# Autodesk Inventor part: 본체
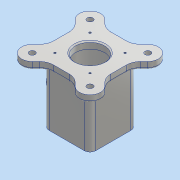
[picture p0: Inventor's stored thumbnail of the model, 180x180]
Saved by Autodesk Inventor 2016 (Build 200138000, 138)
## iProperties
Created: 2019-11
Part Number: 본체
Material: 알루미늄 6061
Document SubType Name: Modeling
Designer: user
Density: 2.7 g/cm^3
Appearance: 알루미늄 - 평지
Mass: 1074.3 g
Surface Area: 878.245 cm^2
Volume: 397.89 cm^3
Author: user
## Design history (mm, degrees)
sketch "스케치1"
  geometry: L1 (49, -49)-(-49, -49); L2 (-49, -49)-(-49, 49); L3 (-49, 49)-(49, 49); L4 (49, 49)-(49, -49); L5 (49, -49)-(-49, 49); L6 (-49, -49)-(49, 49); L7 (49.497, -49.497)-(-49.497, 49.497); L8 (62.225, -36.77)-(-36.77, 62.225); L9 (-62.225, 36.77)-(36.77, -62.225); L10 (-49.497, -49.497)-(49.497, 49.497); L11 (-36.77, -62.225)-(62.225, 36.77); L12 (36.77, 62.225)-(-62.225, -36.77); A1 r 18 centre (49.497, -49.497) between (36.77, -62.225) and (62.225, -36.77); A2 r 18 centre (-49.497, 49.497) between (-36.77, 62.225) and (-62.225, 36.77); A3 r 18 centre (-49.497, -49.497) between (-62.225, -36.77) and (-36.77, -62.225); A4 r 18 centre (49.497, 49.497) between (62.225, 36.77) and (36.77, 62.225); 1 further point
  constraints: 28 end point, 8 point on circle, 8 tangent, 4 centre point, 4 midpoint, 4 parallel, 2 point on line, 1 horizontal, 1 perpendicular
  dimensions: "d0" = 98 distance of L2.end L3.end; "d1" = 98 distance of L3.end L1.start; "d2" = 36 distance between parallel lines of L11 L12; "d3" = 36 distance between parallel lines of L9 L8; "d4" = 70 distance of L7.start point (0, 0); "d5" = 70 distance of L10.start point (0, 0)
extrude "돌출1" new body sketch "스케치1" distance "d6" = 12; taper "d7" = 0 deg
sketch "스케치2"
  geometry: L1 (30, -30)-(-30, -30); L2 (-30, -30)-(-30, 30); L3 (-30, 30)-(30, 30); L4 (30, 30)-(30, -30); L5 (30, -30)-(-30, 30); L6 (-30, -30)-(30, 30); L7 (23.544, 49)-(-23.544, 49) reference; L8 (-23.544, 49)-(-36.77, 62.225) reference; L9 (-62.225, 36.77)-(-49, 23.544) reference; L10 (-49, 23.544)-(-49, -23.544) reference; L11 (-49, -23.544)-(-62.225, -36.77) reference; L12 (-36.77, -62.225)-(-23.544, -49) reference; L13 (-23.544, -49)-(23.544, -49) reference; L14 (23.544, -49)-(36.77, -62.225) reference; L15 (62.225, -36.77)-(49, -23.544) reference; L16 (49, -23.544)-(49, 23.544) reference; L17 (49, 23.544)-(62.225, 36.77) reference; L18 (36.77, 62.225)-(23.544, 49) reference; A1 r 18 centre (-49.497, 49.497) between (-36.77, 62.225) and (-62.225, 36.77) reference; A2 r 18 centre (-49.497, -49.497) between (-62.225, -36.77) and (-36.77, -62.225) reference; A3 r 18 centre (49.497, -49.497) between (36.77, -62.225) and (62.225, -36.77) reference; A4 r 18 centre (49.497, 49.497) between (62.225, 36.77) and (36.77, 62.225) reference; 5 further points
  constraints: 12 end point, 4 coincident, 2 midpoint, 2 parallel, 1 horizontal, 1 perpendicular
  dimensions: "d8" = 60 distance of L2.end L3.end; "d9" = 60 distance of L3.end L1.start
hole "구멍1" sketch "스케치2" at (-30, 30), (30, 30), (30, -30), (-30, -30) diameter "d10" = 3.459; stored, may be unused: countersink angle "d14" = 90 deg, drill point angle "d16" = 118 deg; dims "d11" = 8, "d12" = 4, "d13" = 2, "d15" = 10
sketch "스케치3"
  geometry: L1 (-40, -40)-(40, -40); L2 (40, -40)-(40, 40); L3 (40, 40)-(-40, 40); L4 (-40, 40)-(-40, -40); L5 (-40, -40)-(40, 40); L6 (40, -40)-(-40, 40); 1 further point
  constraints: 12 end point, 2 midpoint, 2 parallel, 1 horizontal, 1 perpendicular
  dimensions: "d17" = 80 distance of L1.end L2.end; "d18" = 80 distance of L1.start L1.end
extrude "돌출2" join sketch "스케치3" distance "d19" = 98; taper "d20" = 0 deg
node "작업 평면1"
sketch "스케치5"
  geometry: L1 (40, 12)-(40, -98); L2 (0, -98)-(80, -98) reference; L3 (16.456, 12)-(3.23, 12) reference; L4 (15, 12)-(15, 0); L5 (15, 0)-(5, 0); L6 (5, 0)-(5, -86); L7 (5, -86)-(15, -86); L8 (15, -86)-(15, -98); L9 (63.544, 12)-(16.456, 12) reference; L10 (15, 12)-(40, 12); L11 (15, -98)-(40, -98); 1 further point
  constraints: 16 end point, 5 point on line, 4 perpendicular, 1 midpoint, 1 vertical
  dimensions: "d27" = 110 distance of L1.start L1.end; "d28" = 50 diameter of L4 L1; "d29" = 70 diameter of L6 L1; "d30" = 12 distance of L4.start L4.end; "d31" = 12 distance of L7.end L8.end
revolve "회전2" sketch "스케치5" stored, may be unused: angle "d32" = 90 deg
sketch "스케치6"
  geometry: A1 r 18 centre (-49.497, -49.497) between (-62.225, -36.77) and (-36.77, -62.225) reference; A2 r 18 centre (49.497, -49.497) between (36.77, -62.225) and (62.225, -36.77) reference; A3 r 18 centre (49.497, 49.497) between (62.225, 36.77) and (36.77, 62.225) reference; A4 r 18 centre (-49.497, 49.497) between (-36.77, 62.225) and (-62.225, 36.77) reference; 5 further points
  constraints: 4 coincident
hole "구멍2" sketch "스케치6" at (-49.497, -49.497), (49.497, -49.497), (49.497, 49.497), (-49.497, 49.497) diameter "d33" = 10; stored, may be unused: countersink angle "d37" = 90 deg, drill point angle "d39" = 118 deg; dims "d34" = 8, "d35" = 18, "d36" = 4, "d38" = 12
node "작업 평면2"
sketch "스케치9"
  geometry: C1 r 20 at (0, -49); 1 further point
  constraints: 1 centre point, 1 vertical alignment
  dimensions: "d41" = 40 diameter of C1; "d42" = 49 distance of point (0, 0) C1.centre
extrude "돌출3" join sketch "스케치9" distance "d43" = 20; taper "d44" = 0 deg
sketch "스케치10"
  geometry: C1 r 20 at (0, 0) reference; C2 r 15 at (0, 0); 1 further point
  constraints: 1 centre point, 1 coincident
  dimensions: "d45" = 30 diameter of C2
extrude "돌출4" cut sketch "스케치10" distance "d46" = 8; taper "d47" = 0 deg
sketch "스케치11"
  geometry: C1 r 15 at (0, 0) reference; C2 r 12.5 at (0, 0); 1 further point
  constraints: 1 centre point, 1 coincident
  dimensions: "d48" = 25 diameter of C2
extrude "돌출5" cut sketch "스케치11" stored distance "d49" = 8; taper "d50" = 0 deg
fillet "모깎기1" dims "d51" = 10
chamfer "모따기1" distance "d52" = 2; stored, may be unused: second distance "d53" = 2, angle "d54" = 45 deg
fillet "모깎기2" dims "d55" = 25
fillet "모깎기3" dims "d56" = 3
chamfer "모따기2" distance "d57" = 2; stored, may be unused: second distance "d58" = 2, angle "d59" = 45 deg
fillet "모깎기4" dims "d60" = 3
sketch "스케치12"
  geometry: L1 (110, 43.189)-(110, 16.811) reference; L2 (0, 0)-(0, 60) reference; 3 further points
  constraints: 1 horizontal alignment, 1 midpoint, 1 other
  dimensions: "d61" = 10 distance from line of L2 point (10, 30)
extrude "돌출6" join sketch "스케치12" distance "d62" = 0.5; taper "d63" = 0 deg
sketch "스케치13"
  geometry: C1 r 1.73 at (30, 30) reference; C2 r 1.73 at (30, -30) reference; C3 r 1.73 at (-30, -30) reference; C4 r 1.73 at (-30, 30) reference; 5 further points
  constraints: 4 coincident
hole "구멍3" sketch "스케치13" at (30, 30), (30, -30), (-30, -30), (-30, 30) diameter "d64" = 3.459; stored, may be unused: countersink angle "d68" = 90 deg, drill point angle "d70" = 118 deg; dims "d65" = 8, "d66" = 19.05, "d67" = 4.775, "d69" = 10
node "솔리드1"
node "투영된 루프1"
other parameters: "d40" = -55
